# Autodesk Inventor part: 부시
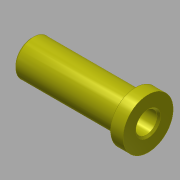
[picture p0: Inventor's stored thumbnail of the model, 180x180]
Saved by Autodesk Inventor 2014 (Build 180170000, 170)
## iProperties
Created: 2016-11
Part Number: 부시
Material: 강철, 연강
Document SubType Name: Modeling
Designer: mduedu
Density: 1 g/cm^3
Appearance: 노란색
Author: mduedu
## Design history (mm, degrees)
sketch "스케치1"
  geometry: L1 (0, 0)-(65, 0); L2 (65, 0)-(65, 14); L3 (65, 14)-(58, 14); L4 (58, 14)-(58, 10); L5 (58, 10)-(0, 10); L6 (0, 10)-(0, 0)
  constraints: 12 end point, 3 parallel, 2 perpendicular, 1 horizontal
  dimensions: "d0" = 65 distance of L1.start L1.end; "d1" = 7 distance of L2.end L3.end; "d2" = 28 diameter of L3 L1; "d3" = 20 diameter of L5 L1
revolve "회전1" sketch "스케치1" stored, may be unused: angle "d4" = 90 deg
hole "구멍1" diameter "d7" = 12; stored, may be unused: countersink angle "d11" = 90 deg, drill point angle "d13" = 118 deg; dims "d5" = 10, "d6" = 10, "d8" = 6, "d9" = 4, "d10" = 2, "d12" = 8
chamfer "모따기1" distance "d14" = 1; stored, may be unused: second distance "d15" = 2, angle "d16" = 45 deg
node "솔리드1"
